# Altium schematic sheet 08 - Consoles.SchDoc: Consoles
size A3; PageSetup: Record=PageOptions¦CenterHorizontal=True¦CenterVertical=True¦PrintScale=0.70¦XCorrection=1.00¦YCorrection=1.00¦PrintKind=0¦BorderSize=5000000¦LeftOffset=0¦BottomOffset=0¦Orientation=2¦PaperLength=4200¦PaperWidth=2970¦Scale=100¦PaperSource=7¦PrintQuality=600¦MediaType=1¦DitherType=10¦PaperKind=A4¦PrintScaleMode=1; Author: Juan Anzola; SheetNumber: 8; SheetTotal: 21
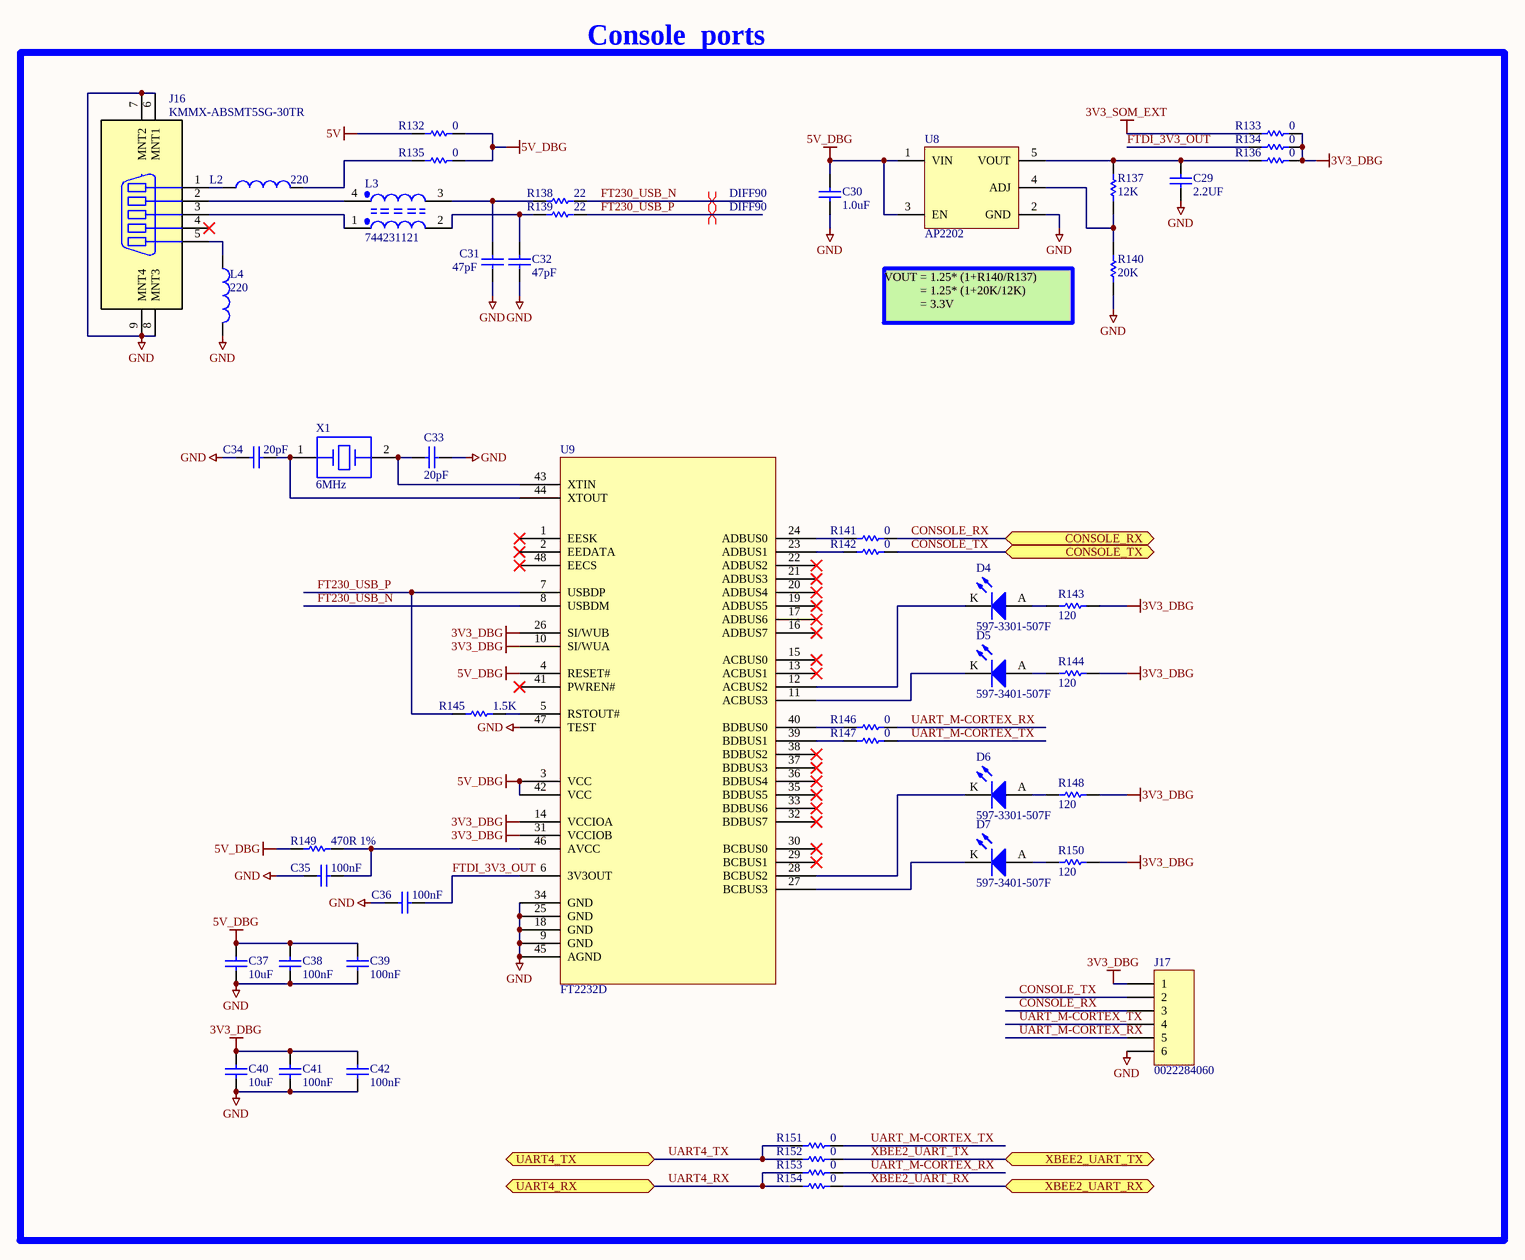
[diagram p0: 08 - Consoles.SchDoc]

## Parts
C29  2.2UF  [CAPC1608X90N]
C30  1.0uF  [CAPC1005X55N]
C31  47pF  [CAPC1005X55N]
C32  47pF  [CAPC1005X55N]
C33  20pF  [CAPC1608X90N]
C34  20pF  [CAPC1608X90N]
C35  100nF  [CAPC1005X55N]
C36  100nF  [CAPC1005X55N]
C37  10uF  [CAPC1005X55N]
C38  100nF  [CAPC1005X55N]
C39  100nF  [CAPC1005X55N]
C40  10uF  [CAPC1005X55N]
C41  100nF  [CAPC1005X55N]
C42  100nF  [CAPC1005X55N]
D4  597-3301-507F  [LEDM3020X130N_GREEN]
D5  597-3401-507F  [LEDM3020X130N_YELLOW]
D6  597-3301-507F  [LEDM3020X130N_GREEN]
D7  597-3401-507F  [LEDM3020X130N_YELLOW]
J16  KMMX-ABSMT5SG-30TR  [KYCON_KMMX-ABSMT5]
J17  0022284060  [MOLEX_0022284060]
L2  220  [INDC2013X110N]
L3  744231121  [FIL_DLW21H]
L4  220  [INDC2013X110N]
R132  0  [RESC1609X55N]
R133  0  [RESC1609X55N]
R134  0  [RESC1609X55N]
R135  0  [RESC1609X55N]
R136  0  [RESC1609X55N]
R137  12K  [RESC1609X55N]
R138  22  [RESC1005X40N]
R139  22  [RESC1005X40N]
R140  20K  [RESC1609X55N]
R141  0  [RESC1609X55N]
R142  0  [RESC1609X55N]
R143  120  [RESC1005X40N]
R144  120  [RESC1005X40N]
R145  1.5K  [RESC1005X40N]
R146  0  [RESC1609X55N]
R147  0  [RESC1609X55N]
R148  120  [RESC1005X40N]
R149  470R 1%  [RESC0603X28N]
R150  120  [RESC1005X40N]
R151  0  [RESC1609X55N]
R152  0  [RESC1609X55N]
R153  0  [RESC1609X55N]
R154  0  [RESC1609X55N]
U8  AP2202  [SOT95P280X145-5N]
U9  FT2232D  [QFP50P900X900X160-48N]
X1  6MHz  [XTAL_ XT9M20HRR]

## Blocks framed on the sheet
Console  ports: C29-C42 D4-D7 J16 J17 L2-L4 R132-R154 U8 U9 X1

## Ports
CONSOLE_RX (bidir), CONSOLE_TX (bidir), UART4_RX (bidir), UART4_TX (bidir), XBEE2_UART_RX (bidir), XBEE2_UART_TX (bidir)

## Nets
3V3_DBG: C40.2 C41.2 C42.2 J17.1 R133.2 R134.2 R136.2 R143.1 R144.1 R148.1 R150.1 U9.10(SI/WUA) U9.14(VCCIOA) U9.26(SI/WUB) U9.31(VCCIOB)
3V3_SOM_EXT: R133.1
5V: R132.1
5V_DBG: C30.2 C37.2 C38.2 C39.2 R132.2 R135.2 R149.1 U8.1(VIN) U8.3(EN) U9.3(VCC) U9.4(RESET#) U9.42(VCC)
GND: C29.1 C30.1 C31.1 C32.1 C33.1 C34.1 C35.1 C36.2 C37.1 C38.1 C39.1 C40.1 C41.1 C42.1 J16.6(MNT1) J16.7(MNT2) J16.8(MNT3) J16.9(MNT4) J17.6 L4.2 R140.1 U8.2(GND) U9.9(GND) U9.18(GND) U9.25(GND) U9.34(GND) U9.45(AGND) U9.47(TEST)
CONSOLE_RX: J17.3 R141.2 ; port CONSOLE_RX
CONSOLE_TX: J17.2 R142.2 ; port CONSOLE_TX
FT230_USB_N: R138.2 U9.8(USBDM)
FT230_USB_P: R139.2 R145.1 U9.7(USBDP)
FTDI_3V3_OUT: C36.1 R134.1 U9.6(3V3OUT)
UART4_RX: R153.1 R154.1 ; port UART4_RX
UART4_TX: R151.1 R152.1 ; port UART4_TX
UART_M-CORTEX_RX: J17.5 R146.2 R153.2
UART_M-CORTEX_TX: J17.4 R147.2 R151.2
XBEE2_UART_RX: R154.2 ; port XBEE2_UART_RX
XBEE2_UART_TX: R152.2 ; port XBEE2_UART_TX
NetC29_2: C29.2 R136.1 R137.2 U8.5(VOUT)
NetC31_2: C31.2 L3.3 R138.1
NetC32_2: C32.2 L3.2 R139.1
NetC33_2: C33.2 U9.43(XTIN) X1.2
NetC34_2: C34.2 U9.44(XTOUT) X1.1
NetC35_2: C35.2 R149.2 U9.46(AVCC)
NetD4_A: D4.A R143.2
NetD4_K: D4.K U9.12(ACBUS2)
NetD5_A: D5.A R144.2
NetD5_K: D5.K U9.11(ACBUS3)
NetD6_A: D6.A R148.2
NetD6_K: D6.K U9.28(BCBUS2)
NetD7_A: D7.A R150.2
NetD7_K: D7.K U9.27(BCBUS3)
NetJ16_1: J16.1 L2.1
NetJ16_2: J16.2 L3.4
NetJ16_3: J16.3 L3.1
NetJ16_5: J16.5 L4.1
NetL2_2: L2.2 R135.1
NetR137_1: R137.1 R140.2 U8.4(ADJ)
NetR141_1: R141.1 U9.24(ADBUS0)
NetR142_1: R142.1 U9.23(ADBUS1)
NetR145_2: R145.2 U9.5(RSTOUT#)
NetR146_1: R146.1 U9.40(BDBUS0)
NetR147_1: R147.1 U9.39(BDBUS1)

Not connected (* = marked no-connect by the designer): J16 4*; U9 1(EESK)* 2(EEDATA)* 13(ACBUS1)* 15(ACBUS0)* 16(ADBUS7)* 17(ADBUS6)* 19(ADBUS5)* 20(ADBUS4)* 21(ADBUS3)* 22(ADBUS2)* 29(BCBUS1)* 30(BCBUS0)* 32(BDBUS7)* 33(BDBUS6)* 35(BDBUS5)* 36(BDBUS4)* 37(BDBUS3)* 38(BDBUS2)* 41(PWREN#)* 48(EECS)*

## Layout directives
differential pair; net class DIFF90: FT230_USB_N, FT230_USB_P

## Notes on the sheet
- VOUT = 1.25* (1+R140/R137)
  = 1.25* (1+20K/12K)
  = 3.3V

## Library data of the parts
C29 = 1001303: CAP CER 2.2UF 16V 10% X5R 0603; Part_Type: Capacitor; Manufacturer: TDK Corporation; Manufacturer_Part_Number: C1608X5R1C225K080AB; Digi_PN: 14050730; Component_Life_Cycle_State: Reviewed; Area: 2,27; Project: Pinnacle
C30 = 1001167: CAP CER 1UF 10V 10% X5R 0402; Part_Type: Capacitor; Manufacturer: Murata; Manufacturer_Part_Number: GRM155R61A105KE15D; Digi_PN: 14050399; Component_Life_Cycle_State: Reviewed; Area: 0,95
C31 C32 = 1000007: CAP 47pF 50V 5% NP0 0402; Part_Type: Capacitor; Manufacturer: Murata; Manufacturer_Part_Number: GRM1555C1H470JA01D; Manufacturer_Alt_1: AVX Corporation; Manufacturer_Alt_1_Part_Number: 04025A470JAT2A; Note: 14050747 is Digi No. for GE WDNU; Digi_PN: 14050309; Component_Life_Cycle_State: CAD Reviewed; Area: 0,95; Project: KITT; Temp_Coef: C0G, NP0
C33 C34 = 1002726: CAP CER 20PF 50V C0G/NP0 0603; Part_Type: Capacitor; Manufacturer: Murata; Manufacturer_Part_Number: GRM1885C1H200JA01D; Digi_PN: 14050657; Component_Life_Cycle_State: Reviewed; Area: 2,27; Tolerance: 5%; Temp_Coef: C0G, NP0; Project: DIGI CC8X SOM
C35 C36 C38 C39 C41 C42 = 1000006: CAP 100nF 16V 10% X7R 0402; Part_Type: Capacitor; Manufacturer: Murata; Manufacturer_Part_Number: GRM155R71C104KA88D; Digi_PN: 14050552; Component_Life_Cycle_State: CAD Reviewed; Area: 0,95; Project: KITT; Tolerance: 10
C37 C40 = 1001168: CAP CER 10UF 10V 20% X5R 0402; Part_Type: Capacitor; Manufacturer: Samsung; Manufacturer_Part_Number: CL05A106MP5NUNC; Digi_PN: 14050689; Component_Life_Cycle_State: Reviewed; Area: 0,95; Project: CCWMX6_SBC board
D4 D6 = 1001189: LED GREEN 573NM 1208 SMD; Manufacturer: Dialight; Note: 17050846 = Digi PN for GE WDNU II; Digi_PN: 17050183; Component_Life_Cycle_State: Reviewed; Area: 6
D5 D7 = 1001188: LED YELLOW 588NM 1208 SMD; Manufacturer: Dialight; Note: 17050842 = Digi No. for GE WDNU; Digi_PN: 17050387; Component_Life_Cycle_State: Reviewed; Area: 6
J16 = 1001117: CONN RECEPT MICRO-USB TYPE AB R/A; Part_Type: Connector; Manufacturer: KYCON; Digi_PN: 18000401; Component_Life_Cycle_State: Reviewed; Area: 40
J17 = 1002721: CONN HEADER VERT 6POS 2.54MM; Part_Type: Connector; Manufacturer: Molex; Digi_PN: 0790004; Component_Life_Cycle_State: Pending; Area: 42,49
L2 = 1001174: FERRITE BEAD 220 OHM 2.0A 0805; Manufacturer: Wurth Electronics Inc; Manufacturer_Part_Number: 742792022; Digi_PN: 21000146; Component_Life_Cycle_State: Reviewed; Area: 4.24; Project: CCWMX6_SBC board
L3 = 1001173: CHOKE COM MODE 120 OHM .37A; Part_Type: Inductor; Manufacturer: Wurth Electronics Inc; Digi_PN: 21000143; Component_Life_Cycle_State: Reviewed; Area: 2,4
L4 = 1001174: FERRITE BEAD 220 OHM 2.0A 0805; Manufacturer: Wurth Electronics Inc; Manufacturer_Part_Number: 742792022; Digi_PN: 21000146; Component_Life_Cycle_State: Reviewed; Area: 4,24
R132-R136 R141 R142 R146 R147 R151-R154 = 1000208: RES 0.0 OHM 1/10W 0603; Part_Type: Resistor; Manufacturer: Panasonic - ECG; Manufacturer_Part_Number: ERJ-3GEY0R00V; Note: 13051103 = Digi No. for GE WDNU; Digi_PN: 13050568; Component_Life_Cycle_State: Reviewed; Area: 2,5; Voltage: 75V
R137 = 1001200: RES 12.0K OHM 1/10W 1% 0603 SMD; Part_Type: Resistor; Manufacturer: Yageo; Manufacturer_Part_Number: RC0603FR-0712KL; Digi_PN: 13050531; Component_Life_Cycle_State: Reviewed; Area: 2,5; Project: LuCoV2; Power_WV_SRF: 100; Tolerance: 1
R138 R139 = 1000601: RES 22.0 OHM 1/10W 1% 0402 SMD; Part_Type: Resistor; Manufacturer: Panasonic - ECG; Manufacturer_Part_Number: ERJ-2RKF22R0X; Digi_PN: 13051089; Component_Life_Cycle_State: CAD Reviewed; Area: 0,95; Project: KITT; Power_WV_SRF: 100
R140 = 1000142: RES 20K OHM 1/10W 5% 0603 SMD; Part_Type: Resistor; Manufacturer: Panasonic - ECG; Manufacturer_Part_Number: ERJ-3GEYJ203V; Digi_PN: 13050013; Component_Life_Cycle_State: Reviewed; Area: 2,5; Project: Adjustable Foundation; Power_WV_SRF: 100; Tolerance: 5
R143 R144 R148 R150 = 1001158: RES 120 OHM 1/16W 1% 0402 SMD; Part_Type: Resistor; Manufacturer: Yageo; Manufacturer_Part_Number: RC0402FR-07120RL; Digi_PN: 13050832; Component_Life_Cycle_State: Reviewed; Area: 0.95; Project: CCWMX6_SBC board; Note: 13051102 = Digi No. for GE WDNU
R145 = 1001772: SMRES, 1.5K OHM 0.063W 0402 1%; Part_Type: Resistor; Manufacturer: Vishay Dale; Manufacturer_Part_Number: CRCW04021K50FKED; Digi_PN: 13050862; Component_Life_Cycle_State: Reviewed; Area: 2,2; Power_WV_SRF: 63
R149 = 1001000: RES 470 OHM 1/20W 1% 0201 SMD; Part_Type: Resistor; Manufacturer: KOA; Manufacturer_Part_Number: RK73H1HTTC4700F; Manufacturer_Alt_1: Panasonic - ECG; Manufacturer_Alt_1_Part_Number: ERJ-1GNF4700C; Manufacturer_Alt_2_Part_Number: CRCW0201470RFKED; Digi_PN: 13050898; Component_Life_Cycle_State: Reviewed; Area: 0,18; Power_WV_SRF: 50; Tolerance: 1
U8 = 1001979: IC REG LDO ADJ 0.15A SOT25; Part_Type: Regulator; Manufacturer: Diodes, Inc.; Manufacturer_Part_Number: AP2202K-ADJTRG1; Digi_PN: 17050874; Component_Life_Cycle_State: Created; Area: 8,9; Project: iMX6UL+PMIC
U9 = 1002724: IC USB FS DUAL UART/FIFO 48-LQFP; Manufacturer: FTDI Chip; Digi_PN: 16000200; Component_Life_Cycle_State: Pending; Area: 98,01
X1 = 1002725: Crystals 6MHz lo-profile; Part_Type: Crystals-Oscillators; Manufacturer: Vishay Semiconductors; Manufacturer_Part_Number: XT9M20HRR6M; Digi_PN: 20000271; Component_Life_Cycle_State: Pending; Area: 89,92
